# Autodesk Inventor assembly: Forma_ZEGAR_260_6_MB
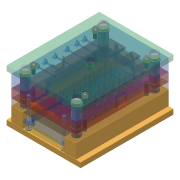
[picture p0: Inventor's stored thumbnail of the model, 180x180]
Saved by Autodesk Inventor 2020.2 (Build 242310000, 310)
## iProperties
Created: 2015-01
Part Number: Forma_ZEGAR_260_6_MB
Document SubType Name: Assembly
Designer: F.Stasiak
Catalog Web Link: www.expertbooks.pl
Manager: www.cadconsulting.pl
Company: Fabian Stasiak CAD Consulting
Author: F.Stasiak
Subject: Zbiór ćwiczeń. Autodesk Inventor 2020. Kurs Professional
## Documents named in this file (19)
- C:\2020_Kurs_Professional\R6 Formy\Komponenty\MB\DME_E 1\Forma_ZEGAR_260_6_MB.iam
- C:\2020_Kurs_Professional\Zasoby\ContentCenter\pl-PL\SM\SM 4x8.ipt
- C:\2020_Kurs_Professional\Zasoby\ContentCenter\pl-PL\EG 100\EG10046-30.ipt
- C:\2020_Kurs_Professional\R6 Formy\Komponenty\MB\DME_E 1\Forma_ZEGAR_260_6_MB_E 700.ipt
- C:\2020_Kurs_Professional\R6 Formy\Komponenty\MB\DME_E 1\Forma_ZEGAR_260_6_MB_E 200_1.ipt
- C:\2020_Kurs_Professional\R6 Formy\Komponenty\MB\DME_E 1\Forma_ZEGAR_260_6_MB_E 300.ipt
- C:\2020_Kurs_Professional\Zasoby\ContentCenter\pl-PL\EG 200\EG 200 42x120.ipt
- C:\2020_Kurs_Professional\Zasoby\ContentCenter\pl-PL\EG 000\EG 000 66-30x55.ipt
- C:\2020_Kurs_Professional\R6 Formy\Komponenty\MB\DME_E 1\Forma_ZEGAR_260_6_MB_RP E.ipt
- C:\2020_Kurs_Professional\Zasoby\ContentCenter\pl-PL\M\M 16x30.ipt
- C:\2020_Kurs_Professional\R6 Formy\Komponenty\MB\DME_E 1\Forma_ZEGAR_260_6_MB_E 110.ipt
- C:\2020_Kurs_Professional\R6 Formy\Komponenty\MB\DME_E 1\Forma_ZEGAR_260_6_MB_E 200.ipt
- C:\2020_Kurs_Professional\R6 Formy\Komponenty\MB\DME_E 1\Forma_ZEGAR_260_6_MB_E 100.ipt
- C:\2020_Kurs_Professional\R6 Formy\Komponenty\MB\DME_E 1\Forma_ZEGAR_260_6_MB_E 600.ipt
- C:\2020_Kurs_Professional\Zasoby\ContentCenter\pl-PL\SB\_SB 3_.ipt
- C:\2020_Kurs_Professional\Zasoby\ContentCenter\pl-PL\M\M 16x140.ipt
- C:\2020_Kurs_Professional\Zasoby\ContentCenter\pl-PL\M\M 10x25.ipt
- C:\2020_Kurs_Professional\R6 Formy\Komponenty\MB\DME_E 1\Forma_ZEGAR_260_6_MB_E 4001.ipt
- C:\2020_Kurs_Professional\R6 Formy\Komponenty\MB\DME_E 1\Forma_ZEGAR_260_6_MB_E 4002.ipt
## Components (45 placed, 18 different names)
1. Forma_ZEGAR_260_4_MB_E 700:1 — Wstaw:6, Równoległy:1, Równoległy:2, Wypchnięcie, Zestawiający:9, Zestawiający:10, Zestawiający:11
2. Forma_ZEGAR_260_4_MB_E 200_1:1 — Wstaw:1, Równoległy:3, Równoległy:4, PL1, Zestawiający:4
3. Forma_ZEGAR_260_4_MB_E 300:1 — Równoległy:5, Równoległy:6, Zestawiający:4, Zestawiający:12, Zestawiający:13
4. Forma_ZEGAR_260_4_MB_E 110:1 — Wstaw:5, Wypchnięcie, Równoległy:7, Zestawiający:5, Równoległy:8, Równoległy:9, Zestawiający:6, Zestawiający:7
5. Forma_ZEGAR_260_4_MB_E 200:1 — Wstaw:2, PL1, Równoległy:10, Równoległy:11, Zestawiający:8, Równoległy:20
6. Forma_ZEGAR_260_4_MB_E 100:1 — Wstaw:4, Zestawiający:8, Równoległy:12, Równoległy:13
7. Forma_ZEGAR_260_4_MB_E 600:1 — Wstaw:3, Równoległy:14, Równoległy:15, Zestawiający:9
8. Forma_ZEGAR_260_4_MB_E 4001:1 — Zestawiający:6, Równoległy:16, Równoległy:18, Zestawiający:12
9. Forma_ZEGAR_260_4_MB_E 4002:2 — Zestawiający:7, Równoległy:17, Równoległy:19, Zestawiający:13
10. Forma_ZEGAR_260_4_MB_RP E:1 — Wstaw:3
11. Forma_ZEGAR_260_4_MB_RP E:2
12. Forma_ZEGAR_260_4_MB_RP E:3
13. Forma_ZEGAR_260_4_MB_RP E:4
14. EG 200 42x120:1 — Równoległy:7, Zestawiający:5
15. EG 200 42x120:2
16. EG 200 42x120:3
17. EG 200 42x120:4
18. M 10x25:1 — Wstaw:6
19. M 10x25:2
20. M 10x25:3
21. M 10x25:4
22. M 16x140:1 — Wstaw:5
23. M 16x140:2
24. M 16x140:3
25. M 16x140:4
26. M 16x30:1 — Wstaw:4
27. M 16x30:2
28. M 16x30:3
29. M 16x30:4
30. SB " 3":1 — Zestawiający:1, Zestawiający:10, Zestawiający:11
31. SB " 3":2
32. SB " 3":3
33. SB " 3":4
34. EG 100 46-30:1 — Wstaw:1
35. EG 100 46-30:2
36. EG 100 46-30:3
37. EG 100 46-30:4
38. SM 4x8:1 — Zestawiający:1
39. SM 4x8:2
40. SM 4x8:3
41. SM 4x8:4
42. EG 000 66-30x55:1 — Wstaw:2
43. EG 000 66-30x55:2
44. EG 000 66-30x55:3
45. EG 000 66-30x55:4
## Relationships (39: Flush 20, Mate 13, Insert 6)
- Wstaw:1 [Insert]: Forma_ZEGAR_260_4_MB_E 200_1:1 ↔ EG 100 46-30:1
- Wstaw:2 [Insert]: Forma_ZEGAR_260_4_MB_E 200:1 ↔ EG 000 66-30x55:1
- Wstaw:3 [Insert]: Forma_ZEGAR_260_4_MB_E 600:1 ↔ Forma_ZEGAR_260_4_MB_RP E:1
- Wstaw:4 [Insert]: Forma_ZEGAR_260_4_MB_E 100:1 ↔ M 16x30:1
- Wstaw:5 [Insert]: Forma_ZEGAR_260_4_MB_E 110:1 ↔ M 16x140:1
- Wstaw:6 [Insert]: Forma_ZEGAR_260_4_MB_E 700:1 ↔ M 10x25:1
- Zestawiający:1 [Mate]: SB " 3":1 ↔ SM 4x8:1
- Równoległy:1 [Flush]: Forma_ZEGAR_260_4_MB_E 700:1
- Równoległy:2 [Flush]: Forma_ZEGAR_260_4_MB_E 700:1
- Wypchnięcie [Mate]: Forma_ZEGAR_260_4_MB_E 700:1 ↔ Forma_ZEGAR_260_4_MB_E 110:1
- Równoległy:3 [Flush]: Forma_ZEGAR_260_4_MB_E 200_1:1
- Równoległy:4 [Flush]: Forma_ZEGAR_260_4_MB_E 200_1:1
- PL1 [Mate]: Forma_ZEGAR_260_4_MB_E 200_1:1 ↔ Forma_ZEGAR_260_4_MB_E 200:1
- Równoległy:5 [Flush]: Forma_ZEGAR_260_4_MB_E 300:1
- Równoległy:6 [Flush]: Forma_ZEGAR_260_4_MB_E 300:1
- Zestawiający:4 [Mate]: Forma_ZEGAR_260_4_MB_E 200_1:1 ↔ Forma_ZEGAR_260_4_MB_E 300:1
- Równoległy:7 [Flush]: Forma_ZEGAR_260_4_MB_E 110:1 ↔ EG 200 42x120:1
- Zestawiający:5 [Mate]: Forma_ZEGAR_260_4_MB_E 110:1 ↔ EG 200 42x120:1
- Równoległy:8 [Flush]: Forma_ZEGAR_260_4_MB_E 110:1
- Równoległy:9 [Flush]: Forma_ZEGAR_260_4_MB_E 110:1
- Zestawiający:6 [Mate]: Forma_ZEGAR_260_4_MB_E 110:1 ↔ Forma_ZEGAR_260_4_MB_E 4001:1
- Zestawiający:7 [Mate]: Forma_ZEGAR_260_4_MB_E 110:1 ↔ Forma_ZEGAR_260_4_MB_E 4002:2
- Równoległy:10 [Flush]: Forma_ZEGAR_260_4_MB_E 200:1
- Równoległy:11 [Flush]: Forma_ZEGAR_260_4_MB_E 200:1
- Zestawiający:8 [Mate]: Forma_ZEGAR_260_4_MB_E 200:1 ↔ Forma_ZEGAR_260_4_MB_E 100:1
- Równoległy:12 [Flush]: Forma_ZEGAR_260_4_MB_E 100:1
- Równoległy:13 [Flush]: Forma_ZEGAR_260_4_MB_E 100:1
- Równoległy:14 [Flush]: Forma_ZEGAR_260_4_MB_E 600:1
- Równoległy:15 [Flush]: Forma_ZEGAR_260_4_MB_E 600:1
- Zestawiający:9 [Mate]: Forma_ZEGAR_260_4_MB_E 700:1 ↔ Forma_ZEGAR_260_4_MB_E 600:1
- Zestawiający:10 [Mate]: Forma_ZEGAR_260_4_MB_E 700:1 ↔ SB " 3":1
- Zestawiający:11 [Mate]: Forma_ZEGAR_260_4_MB_E 700:1 ↔ SB " 3":1
- Równoległy:16 [Flush]: Forma_ZEGAR_260_4_MB_E 4001:1
- Równoległy:17 [Flush]: Forma_ZEGAR_260_4_MB_E 4002:2
- Równoległy:18 [Flush]: Forma_ZEGAR_260_4_MB_E 4001:1
- Równoległy:19 [Flush]: Forma_ZEGAR_260_4_MB_E 4002:2
- Zestawiający:12 [Mate]: Forma_ZEGAR_260_4_MB_E 300:1 ↔ Forma_ZEGAR_260_4_MB_E 4001:1
- Zestawiający:13 [Mate]: Forma_ZEGAR_260_4_MB_E 300:1 ↔ Forma_ZEGAR_260_4_MB_E 4002:2
- Równoległy:20 [Flush]: Forma_ZEGAR_260_4_MB_E 200:1
